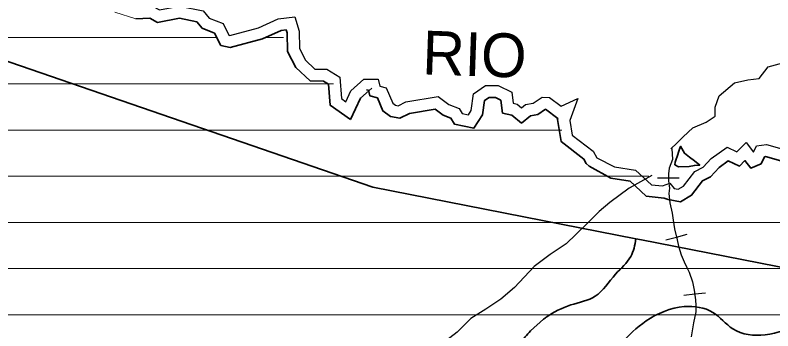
# Model space of a CAD drawing. Extents: x -10.5 to 30.8, y 18.4 to 58.7.
# Drawn here: x 7.549 to 10.83, y 52.185 to 53.552 of the extents above; entities that cross this region are included whole.
import ezdxf

# ---------------------------------------------------------------- set-up
doc = ezdxf.new("R2010")
doc.units = 0
doc.header["$LTSCALE"] = 0.08
doc.linetypes.add('DASH_DOUBLE_DOT', pattern=[9.2, 5, -1.2, 0.3, -1.2, 0.3, -1.2])
for name, color, linetype, lineweight in [('12', 7, 'Continuous', 25), ('20', 7, 'DASH_DOUBLE_DOT', 35), ('28', 7, 'Continuous', 25), ('29', 7, 'Continuous', 13), ('43', 7, 'Continuous', 13), ('47', 7, 'Continuous', 25), ('48', 7, 'Continuous', 35)]:
    doc.layers.add(name, color=color, linetype=linetype, lineweight=lineweight)

msp = doc.modelspace()

# ---------------------------------------------------------------- linework, layer by layer
at = {"layer": '12'}
for p, q in [((10.33028, 52.8481), (10.37773, 52.8478)), ((10.37773, 52.8478), (10.42518, 52.8475)), ((10.41319, 52.5915), (10.45914, 52.60331)), ((10.36723, 52.57968), (10.41319, 52.5915)), ((10.4447, 52.33997), (10.49186, 52.34523)), ((10.49186, 52.34523), (10.53901, 52.3505))]:
    msp.add_line(p, q, dxfattribs=at)
for points in [[(10.3888, 52.97326), (10.4146, 52.99763), (10.44256, 53.02608), (10.48342, 53.06468), (10.54137, 53.08891), (10.58003, 53.11527), (10.58017, 53.15405), (10.59748, 53.20296), (10.66412, 53.25981), (10.72202, 53.2718), (10.77134, 53.2777), (10.81009, 53.32855), (10.88946, 53.35065)], [(10.39248, 52.97454), (10.39578, 52.92758), (10.3805, 52.89015), (10.37784, 52.86517), (10.37765, 52.83516), (10.38247, 52.80263), (10.37981, 52.78014), (10.38458, 52.74011), (10.39432, 52.69507), (10.39915, 52.66504), (10.40393, 52.62751), (10.41616, 52.57994), (10.421, 52.55241), (10.43329, 52.51485), (10.44564, 52.48478), (10.458, 52.45971), (10.46791, 52.43966), (10.48268, 52.39708), (10.48998, 52.36204), (10.49473, 52.31951), (10.49707, 52.2945), (10.4969, 52.26699), (10.48657, 52.21954), (10.47618, 52.15959)], [(10.39248, 52.97454), (10.39578, 52.92758), (10.3805, 52.89015), (10.37784, 52.86517), (10.37765, 52.83516), (10.38247, 52.80263), (10.37981, 52.78014), (10.38458, 52.74011), (10.39432, 52.69507), (10.39915, 52.66504), (10.40393, 52.62751), (10.41616, 52.57994), (10.421, 52.55241), (10.43329, 52.51485), (10.44564, 52.48478), (10.458, 52.45971), (10.46791, 52.43966), (10.48268, 52.39708), (10.48998, 52.36204), (10.49473, 52.31951), (10.49707, 52.2945), (10.4969, 52.26699), (10.48657, 52.21954), (10.47618, 52.15959)]]:
    msp.add_lwpolyline(points, dxfattribs=at)
at = {"layer": '20'}
for points in [[(8.07175, 53.53666), (8.13173, 53.53951), (8.16479, 53.52069), (8.26066, 53.53862), (8.33526, 53.5235), (8.35817, 53.49557), (8.41282, 53.47456), (8.43959, 53.42052), (8.47985, 53.41168), (8.62012, 53.44921), (8.70121, 53.48596), (8.72308, 53.4885), (8.72685, 53.47551), (8.72847, 53.39437), (8.76393, 53.32539), (8.82634, 53.26798), (8.88398, 53.26657), (8.90538, 53.25386), (8.91239, 53.16251), (9.00156, 53.10031), (9.04512, 53.19314), (9.09342, 53.23579)], [(9.07041, 53.22844), (9.07942, 53.22749), (9.08514, 53.20332), (9.11825, 53.19434), (9.14172, 53.13737), (9.175, 53.11342), (9.21532, 53.10566), (9.25707, 53.12708), (9.36746, 53.1458), (9.40215, 53.11951), (9.43613, 53.10673), (9.45202, 53.08007), (9.53592, 53.06345), (9.57313, 53.12106), (9.58114, 53.18228), (9.60164, 53.19586), (9.629, 53.19591), (9.65236, 53.18436), (9.65977, 53.12848), (9.69949, 53.11955), (9.74129, 53.0843), (9.78098, 53.1169), (9.81238, 53.12246), (9.8452, 53.14518), (9.89936, 53.10462), (9.89787, 53.10045), (9.91298, 53.00468), (10.0122, 52.92871), (10.02239, 52.90993)], [(10.03432, 52.89793), (10.1282, 52.8464), (10.21236, 52.83315), (10.28164, 52.76858), (10.35924, 52.76047), (10.37616, 52.75445), (10.43086, 52.74399), (10.47764, 52.77314), (10.5258, 52.83485), (10.56015, 52.85233), (10.59727, 52.89332), (10.63729, 52.92124), (10.68545, 52.89878), (10.70958, 52.92267), (10.73436, 52.89008), (10.77976, 52.90917), (10.79371, 52.93936), (10.79886, 52.94002), (10.86532, 52.92121)]]:
    msp.add_lwpolyline(points, dxfattribs=at)
at = {"layer": '28'}
msp.add_lwpolyline([(10.22638, 52.81357), (10.20776, 52.80334), (10.12393, 52.74162), (10.07814, 52.70244), (10.02258, 52.64703), (9.93578, 52.56163), (9.86646, 52.51602), (9.79681, 52.4633), (9.71199, 52.37292), (9.65216, 52.32236), (9.58737, 52.27903), (9.52273, 52.23807), (9.46255, 52.18021), (9.4121, 52.14113), (9.34548, 52.1099), (9.29568, 52.09218), (9.2455, 52.06515), (9.19073, 52.03311), (9.12063, 51.96852), (9.09834, 51.95844)], dxfattribs=at)
at = {"layer": '29'}
for points in [[(9.08022, 53.22413), (9.04512, 53.19314), (9.00156, 53.10031), (8.91239, 53.16251), (8.90538, 53.25386), (8.88398, 53.26657), (8.82634, 53.26798), (8.76393, 53.32539), (8.72847, 53.39437), (8.72685, 53.47551), (8.72308, 53.4885), (8.70121, 53.48596), (8.62012, 53.44921), (8.47985, 53.41168), (8.43959, 53.42052), (8.41282, 53.47456), (8.35817, 53.49557), (8.33526, 53.5235), (8.26066, 53.53862), (8.16479, 53.52069), (8.13173, 53.53951), (8.07175, 53.53666), (7.98083, 53.56502)], [(10.02239, 52.90993), (10.0122, 52.92871), (9.91298, 53.00468), (9.89787, 53.10045), (9.89936, 53.10462), (9.8452, 53.14518), (9.81238, 53.12246), (9.78098, 53.1169), (9.74129, 53.0843), (9.69949, 53.11955), (9.65977, 53.12848), (9.65236, 53.18436), (9.629, 53.19591), (9.60164, 53.19586), (9.58114, 53.18228), (9.57313, 53.12106), (9.53592, 53.06345), (9.45202, 53.08007), (9.43613, 53.10673), (9.40215, 53.11951), (9.36746, 53.1458), (9.25707, 53.12708), (9.21532, 53.10566), (9.175, 53.11342), (9.14172, 53.13737), (9.11825, 53.19434), (9.08514, 53.20332), (9.08022, 53.22413)], [(10.23078, 52.81598), (10.21236, 52.83315), (10.1282, 52.8464), (10.03432, 52.89793), (10.02239, 52.90993)], [(9.09846, 51.95849), (9.12063, 51.96852), (9.19073, 52.03311), (9.2455, 52.06515), (9.29568, 52.09218), (9.34548, 52.1099), (9.4121, 52.14113), (9.46255, 52.18021), (9.52273, 52.23807), (9.58737, 52.27903), (9.65216, 52.32236), (9.71199, 52.37292), (9.79681, 52.4633), (9.86646, 52.51602), (9.93578, 52.56163), (10.02258, 52.64703), (10.07814, 52.70244), (10.12393, 52.74162), (10.20776, 52.80334), (10.23078, 52.81598)]]:
    msp.add_lwpolyline(points, dxfattribs=at)
at = {"layer": '29', "linetype": 'DASH_DOUBLE_DOT', "lineweight": 35}
for points in [[(8.07175, 53.53666), (8.13173, 53.53951), (8.16479, 53.52069), (8.26066, 53.53862), (8.33526, 53.5235), (8.35817, 53.49557), (8.41282, 53.47456), (8.43959, 53.42052), (8.47985, 53.41168), (8.62012, 53.44921), (8.70121, 53.48596), (8.72308, 53.4885), (8.72685, 53.47551), (8.72847, 53.39437), (8.76393, 53.32539), (8.82634, 53.26798), (8.88398, 53.26657), (8.90538, 53.25386), (8.91239, 53.16251), (9.00156, 53.10031), (9.04512, 53.19314), (9.09342, 53.23579)], [(9.07041, 53.22844), (9.07942, 53.22749), (9.08514, 53.20332), (9.11825, 53.19434), (9.14172, 53.13737), (9.175, 53.11342), (9.21532, 53.10566), (9.25707, 53.12708), (9.36746, 53.1458), (9.40215, 53.11951), (9.43613, 53.10673), (9.45202, 53.08007), (9.53592, 53.06345), (9.57313, 53.12106), (9.58114, 53.18228), (9.60164, 53.19586), (9.629, 53.19591), (9.65236, 53.18436), (9.65977, 53.12848), (9.69949, 53.11955), (9.74129, 53.0843), (9.78098, 53.1169), (9.81238, 53.12246), (9.8452, 53.14518), (9.89936, 53.10462), (9.89787, 53.10045), (9.91298, 53.00468), (10.0122, 52.92871), (10.02239, 52.90993)], [(10.03432, 52.89793), (10.1282, 52.8464), (10.21236, 52.83315), (10.28164, 52.76858), (10.35924, 52.76047), (10.37616, 52.75445), (10.43086, 52.74399), (10.47764, 52.77314), (10.5258, 52.83485), (10.56015, 52.85233), (10.59727, 52.89332), (10.63729, 52.92124), (10.68545, 52.89878), (10.70958, 52.92267), (10.73436, 52.89008), (10.77976, 52.90917), (10.79371, 52.93936), (10.79886, 52.94002), (10.86532, 52.92121)]]:
    msp.add_lwpolyline(points, dxfattribs=at)
at = {"layer": '29', "lineweight": 25}
msp.add_lwpolyline([(10.3068, 52.85771), (10.20776, 52.80334), (10.12393, 52.74162), (10.07814, 52.70244), (10.02258, 52.64703), (9.93578, 52.56163), (9.86646, 52.51602), (9.79681, 52.4633), (9.71199, 52.37292), (9.65216, 52.32236), (9.58737, 52.27903), (9.52273, 52.23807), (9.46255, 52.18021), (9.4121, 52.14113), (9.34548, 52.1099), (9.29568, 52.09218), (9.2455, 52.06515), (9.19073, 52.03311), (9.12063, 51.96852), (9.09834, 51.95844)], dxfattribs=at)
at = {"layer": '43'}
for p, q in [((4.719, 53.4548), (8.42261, 53.4548)), ((8.63244, 53.4548), (8.71137, 53.4548)), ((8.63244, 53.4548), (8.71137, 53.4548)), ((4.719, 53.2548), (8.92708, 53.2548)), ((4.719, 53.0548), (9.91576, 53.0548)), ((10.03432, 52.89793), (10.02239, 52.90993)), ((10.03432, 52.89793), (10.02239, 52.90993)), ((4.719, 52.8548), (10.29326, 52.8548)), ((4.719, 52.6548), (11.74932, 52.6548)), ((4.719, 52.4548), (12.30135, 52.4548)), ((4.719, 52.2548), (12.92186, 52.2548))]:
    msp.add_line(p, q, dxfattribs=at)
for points in [[(9.08022, 53.22413), (9.04512, 53.19314), (9.00156, 53.10031), (8.91239, 53.16251), (8.90538, 53.25386), (8.88398, 53.26657), (8.82634, 53.26798), (8.76393, 53.32539), (8.72847, 53.39437), (8.72685, 53.47551), (8.72308, 53.4885), (8.70121, 53.48596), (8.62012, 53.44921), (8.47985, 53.41168), (8.43959, 53.42052), (8.41282, 53.47456), (8.35817, 53.49557), (8.33526, 53.5235), (8.26066, 53.53862), (8.16479, 53.52069), (8.13173, 53.53951), (8.07175, 53.53666), (7.98083, 53.56502)], [(9.08022, 53.22413), (9.04512, 53.19314), (9.00156, 53.10031), (8.91239, 53.16251), (8.90538, 53.25386), (8.88398, 53.26657), (8.82634, 53.26798), (8.76393, 53.32539), (8.72847, 53.39437), (8.72685, 53.47551), (8.72308, 53.4885), (8.70121, 53.48596), (8.62012, 53.44921), (8.47985, 53.41168), (8.43959, 53.42052), (8.41282, 53.47456), (8.35817, 53.49557), (8.33526, 53.5235), (8.26066, 53.53862), (8.16479, 53.52069), (8.13173, 53.53951), (8.07175, 53.53666), (7.98083, 53.56502)], [(10.02239, 52.90993), (10.0122, 52.92871), (9.91298, 53.00468), (9.89787, 53.10045), (9.89936, 53.10462), (9.8452, 53.14518), (9.81238, 53.12246), (9.78098, 53.1169), (9.74129, 53.0843), (9.69949, 53.11955), (9.65977, 53.12848), (9.65236, 53.18436), (9.629, 53.19591), (9.60164, 53.19586), (9.58114, 53.18228), (9.57313, 53.12106), (9.53592, 53.06345), (9.45202, 53.08007), (9.43613, 53.10673), (9.40215, 53.11951), (9.36746, 53.1458), (9.25707, 53.12708), (9.21532, 53.10566), (9.175, 53.11342), (9.14172, 53.13737), (9.11825, 53.19434), (9.08514, 53.20332), (9.08022, 53.22413)], [(10.02239, 52.90993), (10.0122, 52.92871), (9.91298, 53.00468), (9.89787, 53.10045), (9.89936, 53.10462), (9.8452, 53.14518), (9.81238, 53.12246), (9.78098, 53.1169), (9.74129, 53.0843), (9.69949, 53.11955), (9.65977, 53.12848), (9.65236, 53.18436), (9.629, 53.19591), (9.60164, 53.19586), (9.58114, 53.18228), (9.57313, 53.12106), (9.53592, 53.06345), (9.45202, 53.08007), (9.43613, 53.10673), (9.40215, 53.11951), (9.36746, 53.1458), (9.25707, 53.12708), (9.21532, 53.10566), (9.175, 53.11342), (9.14172, 53.13737), (9.11825, 53.19434), (9.08514, 53.20332), (9.08022, 53.22413)], [(10.86532, 52.92121), (10.79886, 52.94002), (10.79371, 52.93936), (10.77976, 52.90917), (10.73436, 52.89008), (10.70958, 52.92267), (10.68545, 52.89878), (10.63729, 52.92124), (10.59727, 52.89332), (10.56015, 52.85233), (10.5258, 52.83485), (10.47764, 52.77314), (10.43086, 52.74399), (10.37616, 52.75445), (10.35924, 52.76047), (10.28164, 52.76858), (10.21236, 52.83315), (10.1282, 52.8464), (10.03432, 52.89793)], [(10.86532, 52.92121), (10.79886, 52.94002), (10.79371, 52.93936), (10.77976, 52.90917), (10.73436, 52.89008), (10.70958, 52.92267), (10.68545, 52.89878), (10.63729, 52.92124), (10.59727, 52.89332), (10.56015, 52.85233), (10.5258, 52.83485), (10.47764, 52.77314), (10.43086, 52.74399), (10.37616, 52.75445), (10.35924, 52.76047), (10.28164, 52.76858), (10.21236, 52.83315), (10.1282, 52.8464), (10.03432, 52.89793)]]:
    msp.add_lwpolyline(points, dxfattribs=at)
at = {"layer": '47'}
for points in [[(8.11578, 53.60407), (8.14421, 53.59166), (8.17387, 53.57477), (8.26105, 53.59108), (8.36346, 53.57033), (8.38935, 53.53875), (8.45004, 53.51542), (8.47477, 53.46552), (8.47865, 53.46466), (8.60272, 53.49787), (8.68728, 53.53618), (8.76037, 53.54467), (8.7782, 53.48335), (8.77972, 53.40731), (8.80554, 53.35708), (8.84695, 53.31898), (8.8987, 53.31771), (8.95468, 53.28447), (8.96186, 53.19078), (8.9809, 53.1775), (9.00304, 53.22468), (9.05934, 53.27439)], [(9.05934, 53.27439), (9.12112, 53.27487), (9.12819, 53.245), (9.15621, 53.2374), (9.18373, 53.17058), (9.19587, 53.16185), (9.20762, 53.15958), (9.24063, 53.17652), (9.38081, 53.20029), (9.42729, 53.16507), (9.47114, 53.14857), (9.48452, 53.12612), (9.51163, 53.12076), (9.52358, 53.13925), (9.53313, 53.21224), (9.58608, 53.24733), (9.64099, 53.24743), (9.69979, 53.21835), (9.70609, 53.17085), (9.72306, 53.16703), (9.74173, 53.15129), (9.75872, 53.16525), (9.79232, 53.1712), (9.83083, 53.19786), (9.86315, 53.19608), (9.91303, 53.15872), (9.98509, 53.19095), (9.95079, 53.09545), (9.96063, 53.03305), (10.05223, 52.96292), (10.06766, 52.93448)], [(10.06766, 52.93448), (10.1451, 52.89587), (10.23594, 52.88156), (10.30414, 52.81801), (10.35268, 52.81293), (10.38376, 52.82438), (10.4034, 52.80167), (10.42073, 52.79835), (10.44265, 52.81202), (10.49225, 52.87556), (10.52835, 52.89393), (10.56302, 52.93221), (10.63215, 52.98045), (10.67471, 52.96061), (10.71505, 53.00054), (10.74628, 52.95948), (10.75889, 52.98679), (10.80273, 52.99244), (10.88884, 52.96807)]]:
    msp.add_lwpolyline(points, dxfattribs=at)
at = {"layer": '48'}
for p, q in [((9.78104, 52.18534), (9.83705, 52.23551)), ((9.83705, 52.23551), (9.78104, 52.18534))]:
    msp.add_line(p, q, dxfattribs=at)
for points in [[(10.23724, 52.58389), (9.09821, 52.80758), (7.22318, 53.45329), (6.8065, 54.20315), (7.03567, 55.30711), (7.02426, 55.35958)], [(10.46779, 52.8967), (10.49076, 52.90132), (10.51369, 52.90342), (10.49117, 52.9216), (10.46862, 52.93725), (10.44739, 52.95439), (10.43033, 52.98471), (10.42962, 52.9827), (10.42887, 52.98053), (10.42307, 52.96326), (10.41721, 52.94441), (10.41071, 52.92448), (10.40715, 52.91561), (10.40518, 52.90475)], [(10.40518, 52.90475), (10.42097, 52.89514), (10.46779, 52.8967)], [(13.1676, 52.19155), (11.43157, 52.34934), (10.2618, 52.57907), (10.23722, 52.58384)]]:
    msp.add_lwpolyline(points, dxfattribs=at)
for points in [[(9.83705, 52.23551), (9.8483, 52.24387), (9.95515, 52.29734), (10.06136, 52.33521), (10.14907, 52.43106), (10.21503, 52.50684), (10.23724, 52.58389)], [(10.23722, 52.58384), (10.21503, 52.50684), (10.14907, 52.43106), (10.06136, 52.33521), (9.95515, 52.29734), (9.8483, 52.24387), (9.83705, 52.23551)], [(9.65288, 51.32868), (9.76997, 51.37657), (9.84527, 51.42597), (9.95322, 51.50546), (10.08447, 51.64143), (10.20418, 51.75175), (10.30232, 51.72218), (10.43551, 51.77992), (10.48123, 51.87206), (10.59199, 51.89414), (10.66489, 51.88631), (10.79849, 51.82941), (10.89531, 51.76862), (10.97971, 51.66139), (11.07697, 51.61101), (11.18902, 51.53925), (11.21163, 51.45508), (11.1348, 51.36926), (11.0138, 51.35276), (10.92283, 51.30393), (10.89344, 51.22683), (10.93716, 51.14711), (11.02072, 51.14411), (11.18111, 51.22692), (11.30298, 51.26423), (11.43223, 51.22833), (11.53753, 51.12035), (11.65089, 51.07981), (11.7151, 51.11397), (11.75972, 51.1801), (11.75365, 51.28452), (11.7058, 51.39045), (11.61683, 51.51347), (11.55723, 51.58856), (11.45018, 51.65492), (11.35423, 51.73652), (11.23937, 51.86569), (11.09902, 51.88636), (11.06793, 52.01773), (11.0425, 52.15932), (10.96026, 52.19353), (10.79705, 52.16813), (10.65691, 52.194), (10.57097, 52.26482), (10.44651, 52.29012), (10.28177, 52.22831), (10.17294, 52.12801), (10.09523, 52.02138), (10.02265, 51.93555)], [(10.02265, 51.93555), (10.09523, 52.02138), (10.17294, 52.12801), (10.28177, 52.22831), (10.44651, 52.29012), (10.57097, 52.26482), (10.65691, 52.194), (10.79705, 52.16813), (10.96026, 52.19353), (11.0425, 52.15932), (11.06793, 52.01773), (11.09902, 51.88636), (11.23937, 51.86569), (11.35423, 51.73652), (11.45018, 51.65492), (11.55723, 51.58856), (11.61683, 51.51347), (11.7058, 51.39045), (11.75365, 51.28452), (11.75972, 51.1801), (11.7151, 51.11397), (11.65089, 51.07981), (11.53753, 51.12035), (11.43223, 51.22833), (11.30298, 51.26423), (11.18111, 51.22692), (11.02072, 51.14411), (10.93716, 51.14711), (10.89344, 51.22683), (10.92283, 51.30393), (11.0138, 51.35276), (11.1348, 51.36926), (11.21163, 51.45508), (11.18902, 51.53925), (11.07697, 51.61101), (10.97971, 51.66139), (10.89531, 51.76862), (10.79849, 51.82941), (10.66489, 51.88631), (10.59199, 51.89414), (10.48123, 51.87206), (10.43551, 51.77992), (10.30232, 51.72218), (10.20418, 51.75175), (10.08447, 51.64143), (9.95322, 51.50546), (9.84527, 51.42597), (9.76997, 51.37657), (9.65288, 51.32868)], [(9.65288, 51.32868), (9.76997, 51.37657), (9.84527, 51.42597), (9.95322, 51.50546), (10.08447, 51.64143), (10.20418, 51.75175), (10.30232, 51.72218), (10.43551, 51.77992), (10.48123, 51.87206), (10.59199, 51.89414), (10.66489, 51.88631), (10.79849, 51.82941), (10.89531, 51.76862), (10.97971, 51.66139), (11.07697, 51.61101), (11.18902, 51.53925), (11.21163, 51.45508), (11.1348, 51.36926), (11.0138, 51.35276), (10.92283, 51.30393), (10.89344, 51.22683), (10.93716, 51.14711), (11.02072, 51.14411), (11.18111, 51.22692), (11.30298, 51.26423), (11.43223, 51.22833), (11.53753, 51.12035), (11.65089, 51.07981), (11.7151, 51.11397), (11.75972, 51.1801), (11.75365, 51.28452), (11.7058, 51.39045), (11.61683, 51.51347), (11.55723, 51.58856), (11.45018, 51.65492), (11.35423, 51.73652), (11.23937, 51.86569), (11.09902, 51.88636), (11.06793, 52.01773), (11.0425, 52.15932), (10.96026, 52.19353), (10.79705, 52.16813), (10.65691, 52.194), (10.57097, 52.26482), (10.44651, 52.29012), (10.28177, 52.22831), (10.17294, 52.12801), (10.09523, 52.02138), (10.02265, 51.93555)], [(8.18237, 50.39169), (8.22451, 50.44732), (8.24215, 50.49358), (8.27852, 50.61211), (8.29812, 50.70519), (8.39325, 50.85287), (8.50033, 50.91155), (8.62351, 50.98007), (8.74213, 51.06439), (8.88795, 51.17378), (9.02984, 51.18952), (9.15715, 51.23185), (9.23355, 51.30726), (9.3278, 51.43413), (9.34416, 51.57422), (9.3703, 51.69832), (9.42646, 51.79009), (9.48153, 51.85585), (9.5625, 51.91546), (9.64565, 52.0271), (9.73381, 52.13335), (9.78104, 52.18534)]]:
    msp.add_spline(points, degree=3, dxfattribs=at)

# ---------------------------------------------------------------- texts
at = {"layer": '47'}
msp.add_text(' RIO', height=0.1896, rotation=358.02, dxfattribs=at).set_placement((9.23959, 53.29867))

doc.saveas('drawing.dxf')
